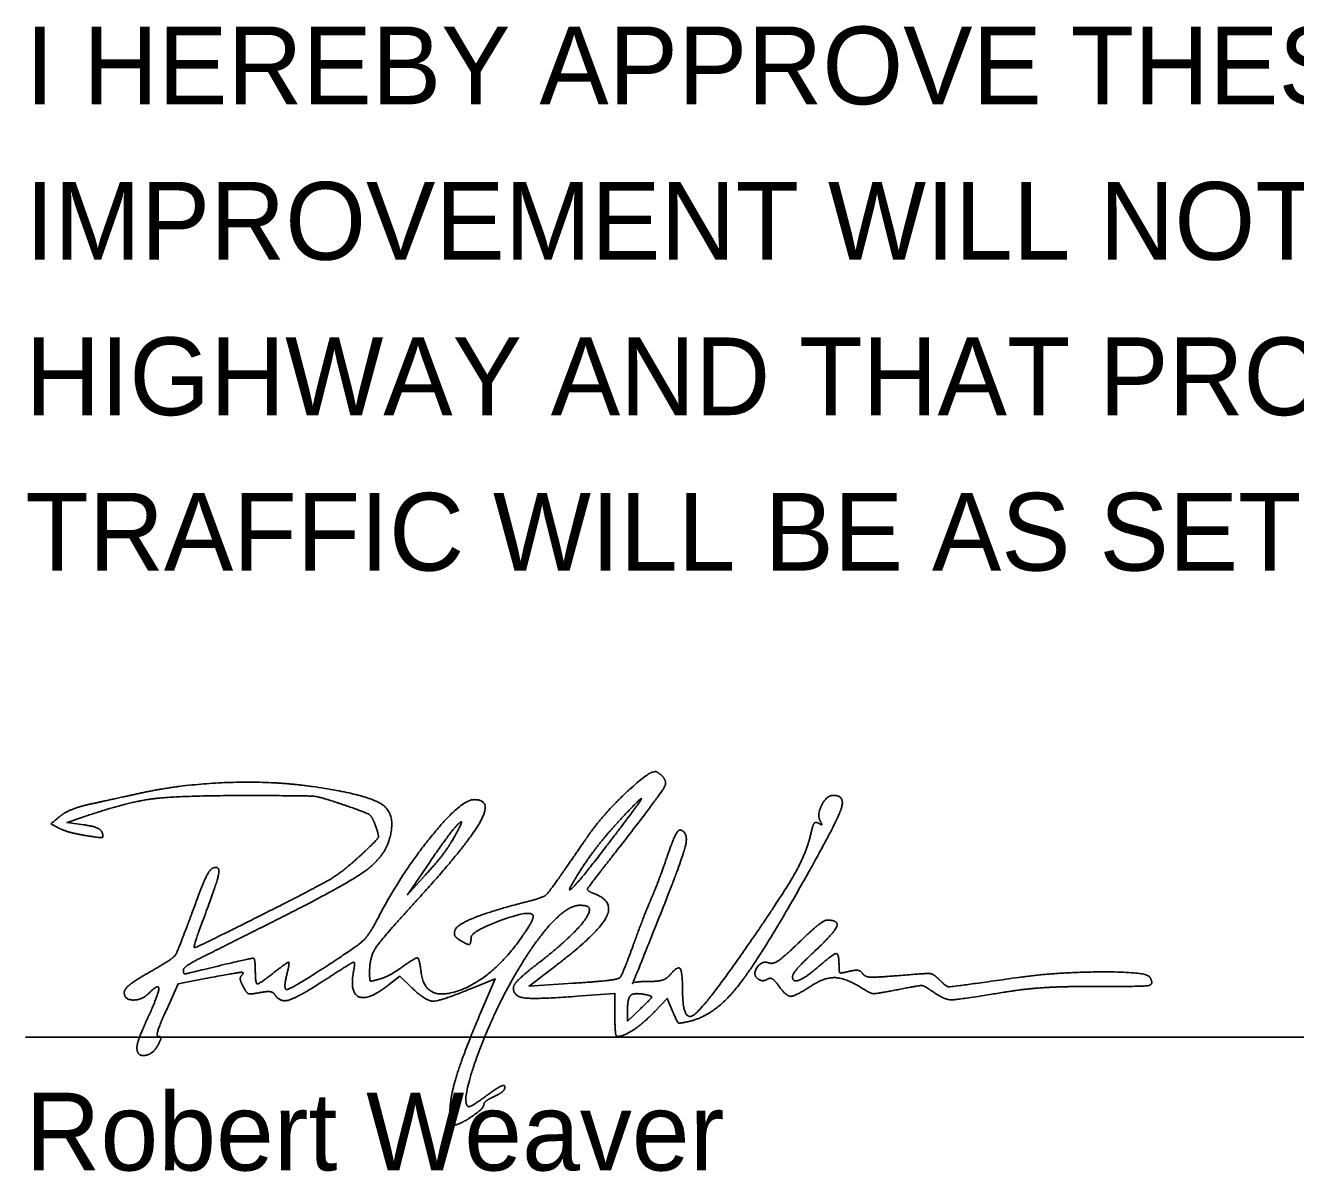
# Model space of a CAD drawing. Extents: x 0 to 34, y 0 to 22.
# Drawn here: x 24.5 to 26.788, y 8.574 to 10.639 of the extents above; entities that cross this region are included whole.
import ezdxf

# ---------------------------------------------------------------- set-up
doc = ezdxf.new("R2010")
doc.units = 0
doc.layers.add('SH_Data', color=7, linetype='Continuous')
doc.layers.add('SH_Text', color=7, linetype='Continuous')

msp = doc.modelspace()

# ---------------------------------------------------------------- linework, layer by layer
at = {"layer": 'SH_Data'}
msp.add_line((24.5, 8.816), (28, 8.816), dxfattribs=at)
at = {"layer": 'SH_Text'}
for points in [[(24.6051, 9.1986), (24.5752, 9.2026), (24.6019, 9.2119)], [(25.2207, 9.1085), (25.1882, 9.0727), (25.2283, 9.1316)], [(25.1537, 8.9099), (25.1743, 8.926), (25.1952, 8.906)], [(25.4866, 8.9132), (25.4075, 8.9081), (25.4561, 8.9453)], [(24.7539, 8.8649), (24.7754, 8.9123), (24.8239, 8.9216)], [(25.3034, 8.9039), (25.346, 8.9214), (25.321, 8.8623)], [(25.4936, 8.8898), (25.5619, 8.895), (25.5619, 8.8562)], [(25.6338, 8.8625), (25.6562, 8.8861), (25.6659, 8.863)], [(25.6081, 8.8675), (25.5847, 8.8451), (25.5847, 8.8658)]]:
    msp.add_lwpolyline(points, dxfattribs=at)
for points in [[(25.6373, 9.2941), (25.6283, 9.2997), (25.541, 9.2182), (25.5135, 9.1786)], [(25.5628, 9.149), (25.6444, 9.2534), (25.6585, 9.281), (25.6373, 9.2941)], [(25.0169, 9.2677), (24.945, 9.2779), (24.781, 9.2717), (24.7085, 9.256)], [(25.1546, 9.1692), (25.1695, 9.2161), (25.1173, 9.2534), (25.0169, 9.2677)], [(24.6019, 9.2119), (24.6801, 9.239), (24.7746, 9.2515), (24.899, 9.2514)], [(24.7085, 9.256), (24.6813, 9.2501), (24.641, 9.2413), (24.6191, 9.2365)], [(24.899, 9.2514), (25.0086, 9.2512), (25.0311, 9.2491), (25.0742, 9.2344)], [(25.5876, 9.2249), (25.6158, 9.2546), (25.6004, 9.2304), (25.5446, 9.1575)], [(25.9001, 9.0939), (25.9599, 9.1998), (25.9782, 9.2518), (25.9555, 9.2518)], [(25.9555, 9.2518), (25.943, 9.2518), (25.9255, 9.2157), (25.9325, 9.2043)], [(24.6191, 9.2365), (24.5971, 9.2316), (24.5716, 9.2216), (24.5624, 9.2141)], [(25.0742, 9.2344), (25.1139, 9.2208), (25.1251, 9.2134), (25.1308, 9.1968)], [(25.3077, 9.244), (25.2843, 9.2438), (25.1741, 9.1068), (25.1332, 9.027)], [(25.2, 9.057), (25.2937, 9.1595), (25.3426, 9.2445), (25.3077, 9.244)], [(25.4981, 9.1138), (25.5162, 9.1424), (25.5556, 9.1913), (25.5876, 9.2249)], [(24.5624, 9.2141), (24.546, 9.2009), (24.546, 9.2003), (24.5604, 9.1927)], [(24.6384, 9.1843), (24.6365, 9.19), (24.6215, 9.1964), (24.6051, 9.1986)], [(25.2283, 9.1316), (25.2675, 9.189), (25.2946, 9.2141), (25.2671, 9.1675)], [(25.929, 9.2014), (25.9237, 9.2046), (25.9186, 9.1985), (25.9157, 9.1854)], [(25.9325, 9.2043), (25.9354, 9.1995), (25.934, 9.1983), (25.929, 9.2014)], [(24.5604, 9.1927), (24.5685, 9.1885), (24.5902, 9.1825), (24.6085, 9.1794)], [(24.6085, 9.1794), (24.6349, 9.1751), (24.6411, 9.1761), (24.6384, 9.1843)], [(25.1308, 9.1968), (25.137, 9.1789), (25.1349, 9.1731), (25.1153, 9.1544)], [(25.5135, 9.1786), (25.5045, 9.1656), (25.4838, 9.1356), (25.4675, 9.112)], [(25.647, 9.0451), (25.6837, 9.1376), (25.6946, 9.1846), (25.6804, 9.1894)], [(25.6804, 9.1894), (25.6765, 9.1907), (25.6659, 9.1701), (25.6568, 9.1437)], [(25.9157, 9.1854), (25.9079, 9.1503), (25.8676, 9.0775), (25.8083, 8.9915)], [(25.1153, 9.1544), (25.0769, 9.1177), (25.0283, 9.0877), (24.9162, 9.0316)], [(24.9371, 9.0198), (25.0695, 9.0861), (25.1447, 9.1378), (25.1546, 9.1692)], [(25.2671, 9.1675), (25.2595, 9.1547), (25.2386, 9.1281), (25.2207, 9.1085)], [(25.5446, 9.1575), (25.498, 9.0968), (25.4715, 9.0718), (25.4981, 9.1138)], [(25.5241, 9.0749), (25.5107, 9.0799), (25.5147, 9.0874), (25.5628, 9.149)], [(25.6568, 9.1437), (25.6478, 9.1172), (25.6344, 9.0819), (25.6272, 9.0651)], [(24.8382, 9.121), (24.8329, 9.1193), (24.8193, 9.0923), (24.8079, 9.061)], [(24.8207, 9.0289), (24.8451, 9.0939), (24.8511, 9.1253), (24.8382, 9.121)], [(25.4675, 9.112), (25.4431, 9.0766), (25.4322, 9.0675), (25.4065, 9.061)], [(25.6968, 8.8449), (25.7406, 8.8552), (25.8204, 8.9529), (25.9001, 9.0939)], [(25.4561, 8.9453), (25.5309, 9.0026), (25.5616, 9.061), (25.5241, 9.0749)], [(25.6272, 9.0651), (25.6199, 9.0483), (25.6053, 9.0106), (25.5947, 8.9813)], [(24.8079, 9.061), (24.7751, 8.9712), (24.7653, 8.9567), (24.7197, 8.931)], [(25.12, 8.9333), (25.12, 8.96), (25.1409, 8.9924), (25.2, 9.057)], [(25.4065, 9.061), (25.3431, 9.0448), (25.278, 9.0194), (25.2741, 9.0093)], [(25.3028, 8.9953), (25.3028, 9.0065), (25.4056, 9.0449), (25.4137, 9.0368)], [(25.3848, 8.933), (25.4185, 8.9904), (25.4781, 9.0537), (25.4984, 9.0537)], [(25.5161, 9.0461), (25.5161, 9.0339), (25.4661, 8.9818), (25.4207, 8.9469)], [(25.4984, 9.0537), (25.5082, 9.0537), (25.5161, 9.0503), (25.5161, 9.0461)], [(25.6252, 8.9165), (25.594, 8.9165), (25.5927, 8.9084), (25.647, 9.0451)], [(24.8048, 8.9775), (24.8029, 8.9775), (24.81, 9.0006), (24.8207, 9.0289)], [(24.9162, 9.0316), (24.8569, 9.0018), (24.8068, 8.9775), (24.8048, 8.9775)], [(24.8171, 8.9596), (24.8349, 8.9685), (24.8889, 8.9956), (24.9371, 9.0198)], [(25.1332, 9.027), (25.119, 8.9994), (25.0949, 8.9779), (25.034, 8.9386)], [(25.4137, 9.0368), (25.4164, 9.0341), (25.4083, 9.0169), (25.3956, 8.9986)], [(25.9441, 9.027), (25.9393, 9.027), (25.9163, 9.0087), (25.8931, 8.9863)], [(25.9208, 8.97), (25.9566, 9.0035), (25.9662, 9.027), (25.9441, 9.027)], [(25.3956, 8.9986), (25.3431, 8.9222), (25.2192, 8.8782), (25.2128, 8.9337)], [(25.2741, 9.0093), (25.2719, 9.0035), (25.2749, 8.9958), (25.2808, 8.9921)], [(25.2808, 8.9921), (25.2959, 8.9825), (25.3028, 8.9835), (25.3028, 8.9953)], [(25.5947, 8.9813), (25.5841, 8.952), (25.5733, 8.9258), (25.5706, 8.9232)], [(25.8083, 8.9915), (25.7261, 8.8722), (25.6838, 8.8414), (25.6838, 8.9008)], [(25.8931, 8.9863), (25.8674, 8.9614), (25.8466, 8.9472), (25.8398, 8.9498)], [(25.8819, 8.9252), (25.8819, 8.9297), (25.8994, 8.9499), (25.9208, 8.97)], [(24.7847, 8.9375), (24.7847, 8.9406), (24.7993, 8.9506), (24.8171, 8.9596)], [(24.9142, 8.9356), (24.9142, 8.958), (24.907, 8.9588), (24.8419, 8.943)], [(24.9707, 8.928), (24.9765, 8.951), (24.9721, 8.9517), (24.9468, 8.9318)], [(25.0331, 8.915), (25.0578, 8.9309), (25.0818, 8.9463), (25.0865, 8.9491)], [(25.0865, 8.9491), (25.092, 8.9524), (25.0937, 8.9478), (25.0913, 8.9353)], [(25.2128, 8.9337), (25.2099, 8.9584), (25.2027, 8.9597), (25.1749, 8.94)], [(25.8398, 8.9498), (25.8266, 8.9549), (25.8091, 8.9277), (25.8209, 8.9204)], [(25.9657, 8.9462), (25.9657, 8.9668), (25.9555, 8.9665), (25.9309, 8.9451)], [(24.7197, 8.931), (24.6968, 8.918), (24.6781, 8.9026), (24.6781, 8.8968)], [(24.8419, 8.943), (24.7887, 8.9302), (24.7847, 8.9298), (24.7847, 8.9375)], [(24.8239, 8.9216), (24.8803, 8.9323), (24.8958, 8.9336), (24.8891, 8.927)], [(24.8891, 8.927), (24.8865, 8.9243), (24.8879, 8.9154), (24.8924, 8.9071)], [(24.9468, 8.9318), (24.9213, 8.9117), (24.9142, 8.9125), (24.9142, 8.9356)], [(25.034, 8.9386), (24.9794, 8.9033), (24.9639, 8.9007), (24.9707, 8.928)], [(25.0913, 8.9353), (25.0838, 8.8959), (25.1181, 8.8819), (25.1537, 8.9099)], [(25.1371, 8.9205), (25.1228, 8.9163), (25.12, 8.9185), (25.12, 8.9333)], [(25.1749, 8.94), (25.1635, 8.932), (25.1465, 8.9232), (25.1371, 8.9205)], [(25.2968, 8.6915), (25.2852, 8.703), (25.3434, 8.8626), (25.3848, 8.933)], [(25.4207, 8.9469), (25.3978, 8.9292), (25.379, 8.9102), (25.379, 8.9048)], [(25.6608, 8.9279), (25.6557, 8.9216), (25.6396, 8.9165), (25.6252, 8.9165)], [(25.6838, 8.9008), (25.6838, 8.9345), (25.675, 8.9449), (25.6608, 8.9279)], [(25.9309, 8.9451), (25.9067, 8.924), (25.8819, 8.914), (25.8819, 8.9252)], [(25.9843, 8.9348), (25.969, 8.9309), (25.9657, 8.933), (25.9657, 8.9462)], [(26.0082, 8.9308), (26.0051, 8.9357), (25.9948, 8.9374), (25.9843, 8.9348)], [(26.0737, 8.9272), (26.0321, 8.9237), (26.0119, 8.9248), (26.0082, 8.9308)], [(26.1465, 8.9196), (26.136, 8.9301), (26.124, 8.9314), (26.0737, 8.9272)], [(26.5253, 8.9247), (26.5196, 8.934), (26.3577, 8.9334), (26.2895, 8.9238)], [(26.4202, 8.9075), (26.5116, 8.9071), (26.5339, 8.9108), (26.5253, 8.9247)], [(24.7221, 8.8951), (24.7406, 8.9135), (24.74, 8.8933), (24.7207, 8.8513)], [(24.8924, 8.9071), (24.8985, 8.8956), (24.9055, 8.8931), (24.9223, 8.8964)], [(24.9487, 8.8934), (24.9578, 8.8787), (24.989, 8.8867), (25.0331, 8.915)], [(25.1952, 8.906), (25.2211, 8.8812), (25.2471, 8.8807), (25.3034, 8.9039)], [(25.379, 8.9048), (25.379, 8.8894), (25.4189, 8.8842), (25.4936, 8.8898)], [(25.5706, 8.9232), (25.5679, 8.9206), (25.5301, 8.9161), (25.4866, 8.9132)], [(25.8209, 8.9204), (25.8251, 8.9178), (25.8322, 8.9179), (25.8368, 8.9207)], [(25.8368, 8.9207), (25.8413, 8.9235), (25.85, 8.9186), (25.8562, 8.9097)], [(25.8562, 8.9097), (25.8702, 8.8899), (25.8868, 8.8895), (25.9153, 8.9083)], [(25.9153, 8.9083), (25.9398, 8.9244), (25.9796, 8.9223), (26.0089, 8.9034)], [(26.0089, 8.9034), (26.0226, 8.8946), (26.0335, 8.8943), (26.0711, 8.9017)], [(26.0711, 8.9017), (26.1106, 8.9094), (26.1192, 8.909), (26.1344, 8.8984)], [(26.2895, 8.9238), (26.1676, 8.9067), (26.1597, 8.9064), (26.1465, 8.9196)], [(26.2628, 8.8971), (26.2984, 8.903), (26.3693, 8.9076), (26.4202, 8.9075)], [(24.6781, 8.8968), (24.6781, 8.8837), (24.7095, 8.8825), (24.7221, 8.8951)], [(24.9223, 8.8964), (24.9343, 8.8988), (24.9462, 8.8975), (24.9487, 8.8934)], [(25.5847, 8.8658), (25.5847, 8.8871), (25.5973, 8.8969), (25.6191, 8.8924)], [(25.6191, 8.8924), (25.629, 8.8904), (25.6267, 8.8852), (25.6081, 8.8675)], [(26.1344, 8.8984), (26.1557, 8.8834), (26.1788, 8.8832), (26.2628, 8.8971)], [(24.7397, 8.8175), (24.7357, 8.8175), (24.742, 8.8388), (24.7539, 8.8649)], [(25.321, 8.8623), (25.289, 8.7863), (25.2647, 8.7076), (25.2647, 8.6795)], [(25.5619, 8.8562), (25.5619, 8.8349), (25.5637, 8.8175), (25.5661, 8.8175)], [(25.5661, 8.8175), (25.5776, 8.8175), (25.6139, 8.8416), (25.6338, 8.8625)], [(25.6659, 8.863), (25.6743, 8.8429), (25.6783, 8.8406), (25.6968, 8.8449)], [(24.7207, 8.8513), (24.7098, 8.8275), (24.7009, 8.8033), (24.7009, 8.7975)], [(24.739, 8.8022), (24.744, 8.8116), (24.7443, 8.8175), (24.7397, 8.8175)], [(24.7009, 8.7975), (24.7009, 8.7814), (24.7298, 8.785), (24.739, 8.8022)], [(25.3638, 8.7265), (25.3638, 8.7312), (25.3494, 8.7245), (25.3319, 8.7116)], [(25.3447, 8.7094), (25.3552, 8.7142), (25.3638, 8.7219), (25.3638, 8.7265)], [(25.3319, 8.7116), (25.3144, 8.6987), (25.2986, 8.6896), (25.2968, 8.6915)], [(25.3257, 8.6942), (25.3257, 8.6978), (25.3342, 8.7047), (25.3447, 8.7094)], [(25.2647, 8.6795), (25.2647, 8.6674), (25.2673, 8.6575), (25.2704, 8.6575)], [(25.2704, 8.6575), (25.2806, 8.6576), (25.3257, 8.6875), (25.3257, 8.6942)]]:
    msp.add_open_spline(points, degree=2, dxfattribs=at)

# ---------------------------------------------------------------- texts
for s, p in [('I HEREBY APPROVE THESE PLANS AND DECLARE THAT THE MAKING OF THIS', (24.5, 10.4966)), ('IMPROVEMENT WILL NOT REQUIRE THE CLOSING TO TRAFFIC OF THE ', (24.5, 10.2166)), ('HIGHWAY AND THAT PROVISIONS FOR THE MAINTENANCE AND SAFETY OF', (24.5, 9.9366)), ('TRAFFIC WILL BE AS SET FORTH ON THE PLANS AND ESTIMATES.', (24.5, 9.6566)), ('Robert Weaver', (24.5, 8.576))]:
    msp.add_text(s, height=0.14, dxfattribs=at).set_placement(p)

doc.saveas('drawing.dxf')
